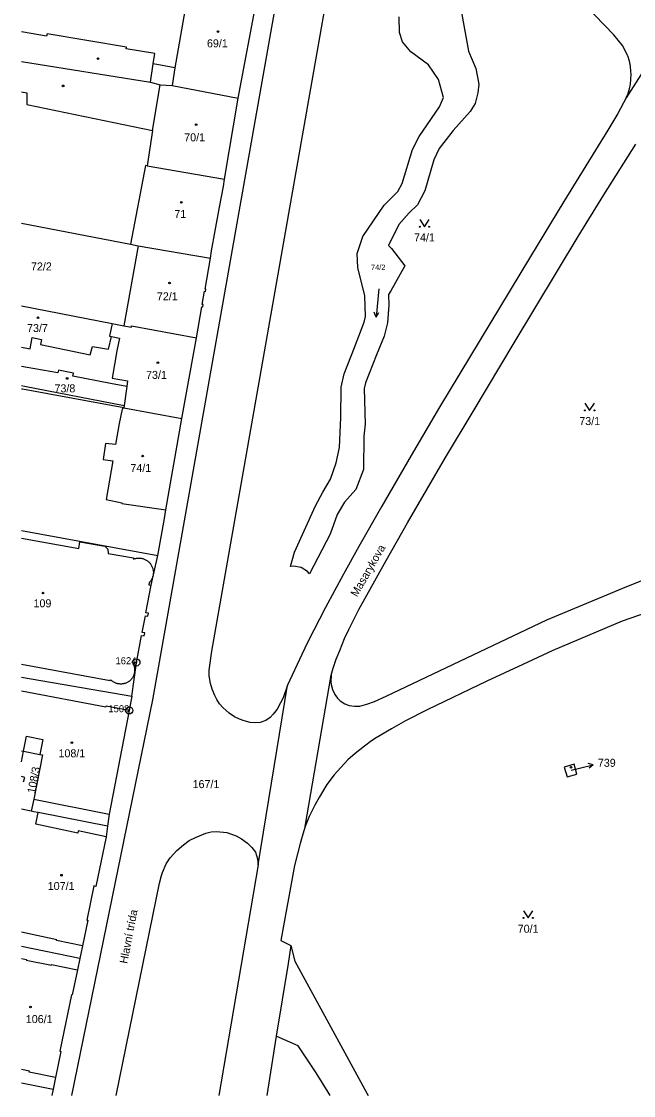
# Model space of a CAD drawing. Extents: x -866441 to -866144, y -1037389 to -1036968.
# Drawn here: x -866440.8 to -866310.8, y -1037388.9 to -1037160.7 of the extents above; entities that cross this region are included whole.
import ezdxf

# ---------------------------------------------------------------- set-up
doc = ezdxf.new("R2010")
doc.units = 0
for name, color, linetype in [('Hranice parcel', 7, 'Continuous'), ('Parcelní čísla', 7, 'Continuous'), ('Pop  PČ popisy', 7, 'Continuous'), ('Vnitřní kresba', 7, 'Continuous'), ('Značky bodu BP', 7, 'Continuous'), ('Značky budov', 7, 'Continuous'), ('Značky kultur', 7, 'Continuous')]:
    doc.layers.add(name, color=color, linetype=linetype)

msp = doc.modelspace()

# ---------------------------------------------------------------- linework, layer by layer
at = {"layer": 'Hranice parcel'}
for p, q in [((-866394.75, -1037177.03), (-866390.49, -1037154.39)), ((-866300.13, -1037157.61), (-866312.39, -1037176.98)), ((-866440.78, -1037169.22), (-866413.41, -1037173.61)), ((-866408.81, -1037174.37), (-866394.75, -1037177.03)), ((-866397.65, -1037194.21), (-866394.75, -1037177.03)), ((-866414.11, -1037191.42), (-866397.65, -1037194.21)), ((-866416.04, -1037208.36), (-866419.03, -1037225.37)), ((-866416.04, -1037208.36), (-866400.69, -1037211.03)), ((-866440.78, -1037221.1), (-866421.51, -1037224.88)), ((-866421.51, -1037224.88), (-866419.03, -1037225.37)), ((-866422.33, -1037230.36), (-866421.68, -1037227.65)), ((-866406.75, -1037245.03), (-866403.62, -1037227.91)), ((-866440.78, -1037229.93), (-866438.91, -1037230.28)), ((-866440.78, -1037233.99), (-866440.78, -1037234)), ((-866418.43, -1037238.24), (-866421.88, -1037237.64)), ((-866419.06, -1037242.77), (-866440.57, -1037238.85)), ((-866418.43, -1037238.24), (-866418.99, -1037242.27)), ((-866418.99, -1037242.27), (-866419.06, -1037242.77)), ((-866419.06, -1037242.77), (-866406.75, -1037245.03)), ((-866440.78, -1037268.84), (-866411.81, -1037274.18)), ((-866380.55, -1037331.74), (-866375.03, -1037299.56)), ((-866390.54, -1037339.89), (-866384.32, -1037301.69)), ((-866440.78, -1037315.62), (-866440.36, -1037315.71)), ((-866440.78, -1037317.99), (-866440.36, -1037315.71)), ((-866323.48, -1037318.51), (-866325.54, -1037319.14)), ((-866438.7, -1037328.47), (-866440.78, -1037328.04))]:
    msp.add_line(p, q, dxfattribs=at)
for points in [[(-866430.07, -1037388.86), (-866412.87, -1037304.8), (-866375.25, -1037091.87), (-866375.18, -1037090.66), (-866375.67, -1037089.29), (-866376.51, -1037088.18), (-866377.58, -1037087.37), (-866379.07, -1037086.89)], [(-866384.32, -1037301.69), (-866385.21, -1037304.38), (-866385.77, -1037305.47), (-866386.48, -1037306.77), (-866387.33, -1037307.83), (-866388.02, -1037308.57), (-866388.93, -1037309.23), (-866390.08, -1037309.63), (-866391.08, -1037309.72), (-866392.26, -1037309.62), (-866393.53, -1037309.3), (-866394.53, -1037308.94), (-866395.58, -1037308.42), (-866396.69, -1037307.68), (-866398.06, -1037306.42), (-866398.71, -1037305.64), (-866399.33, -1037304.73), (-866399.73, -1037303.92), (-866400.33, -1037302.58), (-866400.68, -1037301.33), (-866400.93, -1037299.71), (-866400.97, -1037298.54), (-866400.35, -1037294.48), (-866369.53, -1037118.99)], [(-866313.18, -1037165.84), (-866315.06, -1037163.56), (-866327.2, -1037150.88), (-866340.96, -1037137.11), (-866350.28, -1037128.19), (-866361.44, -1037118.43), (-866362.5, -1037117.65)], [(-866348.34, -1037153.32), (-866345.89, -1037167.01), (-866344.35, -1037170.69), (-866343.71, -1037174.02), (-866343.88, -1037175.92), (-866344.47, -1037178.15), (-866345.56, -1037179.86), (-866349.17, -1037183.87), (-866352.14, -1037187.74), (-866353.21, -1037190.11), (-866355.15, -1037196.7), (-866356.7, -1037199.65), (-866358.5, -1037201.38), (-866360.66, -1037203.89), (-866362.87, -1037208.31), (-866362.21, -1037208.97), (-866359.39, -1037212.62), (-866362.37, -1037217.95), (-866362.88, -1037218.76), (-866362.78, -1037221), (-866363.08, -1037224.77), (-866363.79, -1037227.61), (-866365.38, -1037231.53), (-866367.73, -1037237.49), (-866368.04, -1037238.72), (-866367.81, -1037246.29), (-866368.08, -1037248.82), (-866368.2, -1037255.86), (-866369.79, -1037260.16), (-866372.19, -1037262.81), (-866373.77, -1037265.45), (-866375.25, -1037269.66), (-866379.64, -1037278.03), (-866380.08, -1037277.59), (-866381.44, -1037276.72), (-866383.01, -1037276.43), (-866383.65, -1037276.48), (-866382.84, -1037273.47), (-866378.35, -1037263.61)], [(-866378.35, -1037263.61), (-866376.84, -1037260.73), (-866375.18, -1037257.93), (-866373.98, -1037254.51), (-866373.3, -1037251.25), (-866373, -1037244.87), (-866372.9, -1037238.38), (-866372.25, -1037235.6), (-866370.06, -1037230.01), (-866368.04, -1037224.59), (-866367.77, -1037223.41), (-866367.9, -1037218.99), (-866369.39, -1037212.99), (-866369.49, -1037210.05), (-866368.28, -1037206.41), (-866363.81, -1037199.78), (-866360.91, -1037196.87), (-866359.94, -1037195.17), (-866357.74, -1037187.91), (-866356.37, -1037185.15), (-866352.02, -1037178.88), (-866351.2, -1037176.88), (-866352.28, -1037173.08), (-866354.34, -1037169.95), (-866358.09, -1037167.2), (-866359.92, -1037165.03), (-866360.55, -1037163.1), (-866360.62, -1037159.73)], [(-866312.39, -1037176.98), (-866312.01, -1037176.06), (-866311.98, -1037175.98), (-866311.7, -1037175.03), (-866311.51, -1037174.05), (-866311.43, -1037173.06), (-866311.38, -1037171.96), (-866311.39, -1037171.36), (-866311.49, -1037170.26), (-866311.69, -1037169.18), (-866312.08, -1037168.05), (-866312.11, -1037167.97), (-866312.6, -1037166.88), (-866313.18, -1037165.84)], [(-866413.41, -1037173.61), (-866411.37, -1037174.22), (-866408.81, -1037174.37)], [(-866440.78, -1037175.71), (-866439.65, -1037175.88), (-866439.64, -1037178.4), (-866412.95, -1037183.91), (-866414.11, -1037191.42)], [(-866312.39, -1037176.98), (-866314.18, -1037180.3), (-866316.29, -1037183.83), (-866325.62, -1037199), (-866332.73, -1037210.66), (-866352.05, -1037242.69), (-866358.03, -1037252.91), (-866364.3, -1037263.71), (-866369.17, -1037272.26), (-866372.42, -1037278.16), (-866376.21, -1037285.24), (-866380, -1037292.49), (-866381.27, -1037295.2), (-866384.32, -1037301.69)], [(-866375.03, -1037299.56), (-866374.62, -1037298.06), (-866373.96, -1037296.2), (-866373.2, -1037294.32), (-866372.2, -1037291.8), (-866371.29, -1037289.89), (-866369.19, -1037285.61), (-866363.39, -1037275.2), (-866358.83, -1037267.24), (-866350.73, -1037253.34), (-866344.87, -1037243.59), (-866336.21, -1037228.98), (-866322.61, -1037206.41), (-866317.13, -1037197.53), (-866310.32, -1037186.83)], [(-866414.11, -1037191.42), (-866414.49, -1037191.35), (-866417.67, -1037208.06), (-866416.04, -1037208.36)], [(-866400.69, -1037211.03), (-866400.41, -1037209.46), (-866400.47, -1037209.45), (-866399.69, -1037205.17), (-866399.63, -1037205.18), (-866398.73, -1037200.16), (-866397.93, -1037195.77), (-866397.65, -1037194.21)], [(-866403.62, -1037227.91), (-866402.47, -1037221.31), (-866402.3, -1037221.34), (-866402.22, -1037220.88), (-866402.39, -1037220.84), (-866401.91, -1037218.04), (-866401.73, -1037218.07), (-866401.65, -1037217.59), (-866401.82, -1037217.56), (-866400.69, -1037211.03)], [(-866421.51, -1037224.88), (-866422.07, -1037227.58), (-866421.68, -1037227.65)], [(-866419.03, -1037225.37), (-866417.46, -1037225.68), (-866417.4, -1037225.41), (-866403.62, -1037227.91)], [(-866438.91, -1037230.28), (-866438.5, -1037227.87), (-866436.55, -1037228.27), (-866436.74, -1037229.38), (-866426.21, -1037231.54), (-866425.72, -1037229.74), (-866422.33, -1037230.36)], [(-866421.68, -1037227.65), (-866419.99, -1037227.98), (-866420.52, -1037230.69), (-866421.53, -1037236.51), (-866418.27, -1037237.05), (-866418.43, -1037238.24)], [(-866421.88, -1037237.64), (-866429.89, -1037236.09), (-866429.74, -1037235.42), (-866432.91, -1037234.83), (-866433.09, -1037235.38), (-866439.58, -1037234.21), (-866440.78, -1037233.99)], [(-866440.78, -1037238.06), (-866440.14, -1037238.18), (-866418.99, -1037242.27)], [(-866440.57, -1037238.85), (-866440.78, -1037238.81)], [(-866411.81, -1037274.18), (-866410.39, -1037266.31), (-866410.14, -1037264.44), (-866406.75, -1037245.03)], [(-866417.39, -1037304.04), (-866416.4, -1037296.94), (-866415.29, -1037291.13), (-866414.75, -1037291.24), (-866414.63, -1037290.6), (-866415.17, -1037290.5), (-866414.49, -1037286.94), (-866413.97, -1037287.04), (-866413.85, -1037286.42), (-866414.37, -1037286.32), (-866413.25, -1037280.46), (-866411.81, -1037274.18)], [(-866375.03, -1037299.56), (-866375.13, -1037301.01), (-866375.04, -1037301.56), (-866374.74, -1037302.65), (-866374.28, -1037303.65), (-866373.72, -1037304.45), (-866373.12, -1037305.04), (-866372.13, -1037305.69), (-866371.2, -1037306), (-866370.07, -1037306.19), (-866368.92, -1037306.17), (-866367.46, -1037305.76), (-866365.86, -1037305.16), (-866363.36, -1037304.06), (-866329.22, -1037287.85), (-866312.3, -1037280.78), (-866305.66, -1037278.15)], [(-866308.19, -1037286.36), (-866313.27, -1037288.13), (-866327.97, -1037294.37), (-866334.34, -1037297.29), (-866342.02, -1037300.83), (-866354.66, -1037306.93), (-866359.28, -1037309.3), (-866362.25, -1037310.96), (-866365.45, -1037312.87), (-866366.46, -1037313.55), (-866367.93, -1037314.63), (-866369.92, -1037316.18), (-866371.5, -1037317.58), (-866374.41, -1037320.72), (-866375.94, -1037322.82), (-866377.5, -1037325.43), (-866378.49, -1037327.19), (-866379.7, -1037329.61), (-866380.55, -1037331.74)], [(-866440.78, -1037299.99), (-866417.39, -1037304.04)], [(-866417.39, -1037304.04), (-866417.9, -1037307.07), (-866422.14, -1037329.09), (-866422.5, -1037331.65)], [(-866440.36, -1037315.71), (-866436.9, -1037316.4), (-866436.31, -1037316.51), (-866438.18, -1037325.88), (-866438.7, -1037328.47)], [(-866325.54, -1037319.14), (-866324.91, -1037321.2), (-866322.85, -1037320.57), (-866323.48, -1037318.51)], [(-866422.5, -1037331.65), (-866437.25, -1037328.78), (-866438.14, -1037328.59), (-866438.7, -1037328.47)], [(-866422.5, -1037331.65), (-866422.82, -1037333.9), (-866425, -1037344.43), (-866425.39, -1037344.35), (-866426.89, -1037351.58), (-866426.71, -1037351.62), (-866427.84, -1037357.09), (-866428.41, -1037359.72)], [(-866420.69, -1037388.86), (-866411.47, -1037343.74), (-866411.04, -1037342.16), (-866410.84, -1037341.48), (-866410.04, -1037339.64), (-866409.21, -1037338.38), (-866407.83, -1037336.85), (-866406.39, -1037335.6), (-866405.15, -1037334.72), (-866403.81, -1037334.03), (-866401.68, -1037333.13), (-866400.49, -1037332.85), (-866399.4, -1037332.79), (-866397.16, -1037333.02), (-866395.23, -1037333.7), (-866394.04, -1037334.32), (-866392.79, -1037335.23), (-866391.85, -1037336.15), (-866391.08, -1037337.14), (-866390.68, -1037338.6), (-866390.54, -1037339.89)], [(-866380.55, -1037331.74), (-866381.04, -1037333.38), (-866381.63, -1037335.3), (-866382.22, -1037337.54), (-866382.79, -1037340), (-866385.75, -1037355.96), (-866383.63, -1037357.01)], [(-866390.54, -1037339.89), (-866398.87, -1037388.86)], [(-866428.41, -1037359.72), (-866440.78, -1037357.21)], [(-866383.63, -1037357.01), (-866384.14, -1037360.83), (-866386.69, -1037376.28)], [(-866383.63, -1037357.01), (-866382.73, -1037360.29), (-866367.46, -1037388.33), (-866367.2, -1037388.86)], [(-866428.41, -1037359.72), (-866428.9, -1037362.18), (-866429.99, -1037367.5), (-866430.18, -1037367.46), (-866432.63, -1037379.44), (-866432.45, -1037379.48), (-866433.58, -1037385.01), (-866434.04, -1037387.54)], [(-866386.69, -1037376.28), (-866388.69, -1037388.86)], [(-866375.26, -1037388.86), (-866375.64, -1037388.12), (-866378.21, -1037384.03), (-866382.01, -1037378.31), (-866386.69, -1037376.28)], [(-866440.78, -1037386.16), (-866434.04, -1037387.54)], [(-866434.04, -1037387.54), (-866434.34, -1037388.86)]]:
    msp.add_lwpolyline(points, dxfattribs=at)
at = {"layer": 'Pop  PČ popisy'}
for p, q in [((-866324.05, -1037319.77), (-866322.33, -1037319.34)), ((-866322.33, -1037319.34), (-866319.42, -1037318.61)), ((-866319.42, -1037318.61), (-866320.51, -1037318.37)), ((-866319.42, -1037318.61), (-866320.27, -1037319.34))]:
    msp.add_line(p, q, dxfattribs=at)
at = {"layer": 'Vnitřní kresba'}
for p, q in [((-866405.46, -1037154.78), (-866408.2, -1037170.57)), ((-866435.44, -1037163.88), (-866440.78, -1037162.95)), ((-866435.34, -1037163.34), (-866435.44, -1037163.88)), ((-866418.48, -1037166.22), (-866435.34, -1037163.34)), ((-866418.53, -1037166.54), (-866418.48, -1037166.22)), ((-866412.49, -1037167.52), (-866418.53, -1037166.54)), ((-866412.8, -1037169.75), (-866412.49, -1037167.52)), ((-866413.41, -1037173.61), (-866412.8, -1037169.75)), ((-866408.2, -1037170.57), (-866412.8, -1037169.75)), ((-866408.2, -1037170.57), (-866408.81, -1037174.37)), ((-866412.95, -1037183.91), (-866411.37, -1037174.22)), ((-866440.78, -1037203.58), (-866417.67, -1037208.06)), ((-866419.38, -1037243.07), (-866420.05, -1037246.1)), ((-866419.06, -1037242.77), (-866419.38, -1037243.07)), ((-866420.05, -1037246.1), (-866420.82, -1037250.6)), ((-866422.98, -1037250.34), (-866423.46, -1037253.8)), ((-866420.82, -1037250.6), (-866422.98, -1037250.34)), ((-866423.46, -1037253.8), (-866421.4, -1037254.04)), ((-866421.4, -1037254.04), (-866422.81, -1037262.3)), ((-866422.81, -1037262.3), (-866419.49, -1037263)), ((-866419.49, -1037263), (-866419.51, -1037263.13)), ((-866419.51, -1037263.13), (-866410.14, -1037264.44)), ((-866440.78, -1037270.51), (-866428.64, -1037272.65)), ((-866428.64, -1037272.65), (-866428.39, -1037271.24)), ((-866428.39, -1037271.24), (-866423.11, -1037272.16)), ((-866423.11, -1037272.16), (-866422.47, -1037272.83)), ((-866422.47, -1037272.83), (-866422.4, -1037273.75)), ((-866422.4, -1037273.75), (-866417.01, -1037274.69)), ((-866417.01, -1037274.69), (-866417.04, -1037274.84)), ((-866417.04, -1037274.84), (-866416.84, -1037274.87)), ((-866413.65, -1037279.9), (-866413.74, -1037280.37)), ((-866413.74, -1037280.37), (-866413.25, -1037280.46)), ((-866416.89, -1037296.85), (-866416.99, -1037297.37)), ((-866416.4, -1037296.94), (-866416.89, -1037296.85)), ((-866421.98, -1037300.75), (-866440.78, -1037297.31)), ((-866421.98, -1037300.75), (-866421.95, -1037300.59)), ((-866421.95, -1037300.59), (-866421.77, -1037300.62)), ((-866422.85, -1037306.39), (-866440.78, -1037302.95)), ((-866422.8, -1037306.13), (-866422.85, -1037306.39)), ((-866417.9, -1037307.07), (-866422.8, -1037306.13)), ((-866440.36, -1037315.71), (-866439.72, -1037312.52)), ((-866439.72, -1037312.52), (-866436.26, -1037313.21)), ((-866436.26, -1037313.21), (-866436.9, -1037316.4)), ((-866438.18, -1037325.88), (-866422.14, -1037329.09)), ((-866437.73, -1037331.23), (-866437.25, -1037328.78)), ((-866428.83, -1037333.16), (-866437.73, -1037331.23)), ((-866428.72, -1037332.62), (-866428.83, -1037333.16)), ((-866422.82, -1037333.9), (-866428.72, -1037332.62)), ((-866433.29, -1037355.76), (-866440.78, -1037354.14)), ((-866433.32, -1037355.9), (-866433.29, -1037355.76)), ((-866427.84, -1037357.09), (-866433.32, -1037355.9)), ((-866440.78, -1037359.74), (-866439.73, -1037359.96)), ((-866439.73, -1037359.96), (-866439.76, -1037360.11)), ((-866439.76, -1037360.11), (-866434.44, -1037361.2)), ((-866434.44, -1037361.2), (-866434.41, -1037361.05)), ((-866434.41, -1037361.05), (-866428.9, -1037362.18)), ((-866439.09, -1037383.71), (-866440.78, -1037383.36)), ((-866439.12, -1037383.87), (-866439.09, -1037383.71)), ((-866433.58, -1037385.01), (-866439.12, -1037383.87))]:
    msp.add_line(p, q, dxfattribs=at)
for points in [[(-866416.84, -1037274.87), (-866416.69, -1037274.82), (-866416.54, -1037274.79), (-866416.39, -1037274.76), (-866416.24, -1037274.73), (-866416.09, -1037274.72), (-866415.93, -1037274.71), (-866415.78, -1037274.71), (-866415.62, -1037274.71), (-866415.47, -1037274.73), (-866415.32, -1037274.75), (-866415.17, -1037274.78), (-866415.02, -1037274.82), (-866414.87, -1037274.87), (-866414.73, -1037274.92), (-866414.58, -1037274.98), (-866414.45, -1037275.05), (-866414.31, -1037275.12), (-866414.18, -1037275.2), (-866414.05, -1037275.29), (-866413.93, -1037275.39), (-866413.81, -1037275.48), (-866413.7, -1037275.59), (-866413.59, -1037275.7), (-866413.49, -1037275.82), (-866413.4, -1037275.94), (-866413.31, -1037276.07), (-866413.22, -1037276.2), (-866413.15, -1037276.33), (-866413.08, -1037276.47), (-866413.02, -1037276.61), (-866412.96, -1037276.75), (-866412.92, -1037276.9), (-866412.88, -1037277.05), (-866412.84, -1037277.2), (-866412.82, -1037277.35), (-866412.8, -1037277.5), (-866412.79, -1037277.66), (-866412.79, -1037277.81), (-866412.8, -1037277.97), (-866412.81, -1037278.12), (-866412.83, -1037278.27), (-866412.86, -1037278.42), (-866412.9, -1037278.57), (-866412.94, -1037278.72), (-866412.99, -1037278.87), (-866413.05, -1037279.01), (-866413.12, -1037279.15), (-866413.19, -1037279.28), (-866413.27, -1037279.42), (-866413.35, -1037279.54), (-866413.45, -1037279.67), (-866413.55, -1037279.79), (-866413.65, -1037279.9)], [(-866416.99, -1037297.37), (-866416.93, -1037297.51), (-866416.89, -1037297.66), (-866416.84, -1037297.8), (-866416.81, -1037297.95), (-866416.79, -1037298.1), (-866416.77, -1037298.26), (-866416.76, -1037298.41), (-866416.76, -1037298.56), (-866416.76, -1037298.71), (-866416.78, -1037298.87), (-866416.8, -1037299.02), (-866416.83, -1037299.17), (-866416.87, -1037299.32), (-866416.91, -1037299.46), (-866416.96, -1037299.6), (-866417.02, -1037299.75), (-866417.09, -1037299.88), (-866417.17, -1037300.02), (-866417.25, -1037300.15), (-866417.33, -1037300.27), (-866417.43, -1037300.39), (-866417.53, -1037300.51), (-866417.63, -1037300.62), (-866417.74, -1037300.72), (-866417.86, -1037300.82), (-866417.98, -1037300.91), (-866418.11, -1037301), (-866418.24, -1037301.08), (-866418.38, -1037301.15), (-866418.51, -1037301.22), (-866418.66, -1037301.27), (-866418.8, -1037301.33), (-866418.95, -1037301.37), (-866419.09, -1037301.4), (-866419.24, -1037301.43), (-866419.4, -1037301.45), (-866419.55, -1037301.46), (-866419.7, -1037301.47), (-866419.85, -1037301.46), (-866420.01, -1037301.45), (-866420.16, -1037301.43), (-866420.31, -1037301.4), (-866420.46, -1037301.37), (-866420.6, -1037301.33), (-866420.75, -1037301.28), (-866420.89, -1037301.22), (-866421.03, -1037301.15), (-866421.16, -1037301.08), (-866421.29, -1037301), (-866421.42, -1037300.92), (-866421.54, -1037300.82), (-866421.66, -1037300.72), (-866421.77, -1037300.62)]]:
    msp.add_lwpolyline(points, dxfattribs=at)
at = {"layer": 'Značky bodu BP'}
for centre, radius in [((-866416.38, -1037296.88), 0.75), ((-866416.38, -1037296.88), 0.03), ((-866417.9, -1037307.07), 0.75), ((-866417.9, -1037307.07), 0.03)]:
    msp.add_circle(centre, radius, dxfattribs=at)
at = {"layer": 'Značky budov'}
for centre in [(-866399.07, -1037162.88), (-866424.54, -1037168.63), (-866431.94, -1037174.42), (-866403.7, -1037182.67), (-866406.85, -1037199.16), (-866409.35, -1037216.3), (-866437.29, -1037223.67), (-866411.82, -1037233.22), (-866431.09, -1037236.55), (-866415.06, -1037253.04), (-866436.2, -1037282.14), (-866430.08, -1037313.9), (-866324.12, -1037319.12), (-866432.29, -1037342.07), (-866438.87, -1037370.07)]:
    msp.add_circle(centre, 0.175, dxfattribs=at)
at = {"layer": 'Značky kultur'}
for p, q in [((-866364.95, -1037217.53), (-866365.47, -1037223.51)), ((-866365.47, -1037223.51), (-866365.89, -1037222.49)), ((-866365.47, -1037223.51), (-866364.89, -1037222.58)), ((-866440.1, -1037321.28), (-866440.78, -1037321.08)), ((-866440.38, -1037322.24), (-866440.1, -1037321.28))]:
    msp.add_line(p, q, dxfattribs=at)
for points in [[(-866356.23, -1037202.82), (-866355.23, -1037204.32), (-866354.23, -1037202.82)], [(-866321.16, -1037241.84), (-866320.16, -1037243.34), (-866319.16, -1037241.84)], [(-866334.22, -1037349.65), (-866333.22, -1037351.15), (-866332.22, -1037349.65)]]:
    msp.add_lwpolyline(points, dxfattribs=at)
for centre in [(-866356.23, -1037204.32), (-866354.23, -1037204.32), (-866321.16, -1037243.34), (-866319.16, -1037243.34), (-866334.22, -1037351.15), (-866332.22, -1037351.15)]:
    msp.add_circle(centre, 0.1, dxfattribs=at)

# ---------------------------------------------------------------- texts
at = {"layer": 'Parcelní čísla'}
for s, height, p in [('69/1', 1.7, (-866401.41, -1037166.23)), ('70/1', 1.7, (-866406.24, -1037186.19)), ('71', 1.7, (-866408.34, -1037202.48)), ('74/1', 1.7, (-866357.44, -1037207.45)), ('72/2', 1.7, (-866438.77, -1037213.61)), ('74/2', 1.14, (-866366.58, -1037213.52)), ('72/1', 1.7, (-866412.04, -1037219.96)), ('73/7', 1.7, (-866439.6, -1037226.7)), ('73/1', 1.7, (-866414.34, -1037236.65)), ('73/8', 1.7, (-866433.78, -1037239.51)), ('73/1', 1.7, (-866322.36, -1037246.46)), ('74/1', 1.7, (-866417.66, -1037256.42)), ('109', 1.7, (-866438.23, -1037285.16)), ('108/1', 1.7, (-866432.93, -1037317.02)), ('739', 1.7, (-866318.42, -1037319.04)), ('167/1', 1.7, (-866404.46, -1037323.57)), ('107/1', 1.7, (-866435.21, -1037345.21)), ('70/1', 1.7, (-866335.43, -1037354.28)), ('106/1', 1.7, (-866439.87, -1037373.47))]:
    msp.add_text(s, height=height, dxfattribs=at).set_placement(p)
msp.add_text('108/3', height=1.7, rotation=79, dxfattribs=at).set_placement((-866437.91, -1037324.81))
at = {"layer": 'Pop  PČ popisy'}
for s, rotation, p in [('Masarykova', 60, (-866369.56, -1037283.08)), ('Hlavní trída', 79, (-866418.33, -1037360.95))]:
    msp.add_text(s, height=1.7, rotation=rotation, dxfattribs=at).set_placement(p)
at = {"layer": 'Značky bodu BP'}
for s, p in [('1624', (-866420.83, -1037297.26)), ('1508', (-866422.35, -1037307.45))]:
    msp.add_text(s, height=1.5, dxfattribs=at).set_placement(p)

doc.saveas('drawing.dxf')
